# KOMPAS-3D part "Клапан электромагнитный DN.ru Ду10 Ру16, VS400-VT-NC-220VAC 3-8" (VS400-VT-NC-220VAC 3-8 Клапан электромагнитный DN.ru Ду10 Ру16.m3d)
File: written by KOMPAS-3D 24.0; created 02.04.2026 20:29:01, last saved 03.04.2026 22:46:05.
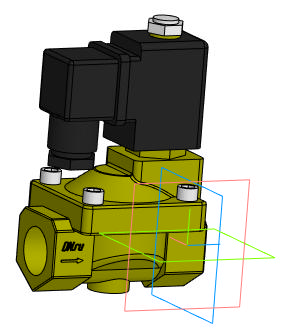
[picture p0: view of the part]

Document properties: Автор: artio; Полное имя файла: C:\Users\artio\OneDrive\Рабочий стол\Клапан электромагнитный DN.ru\VS400-VT-NC\VS400-VT-NC-220VAC 3-8 Клапан электромагнитный DN.ru Ду10 Ру16.m3d

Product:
- Body: Тело 1  | qty 1
    Масса: 1.030062
- Part/product: Клапан электромагнитный DN.ru Ду10 Ру16  | designation VS400-VT-NC-220VAC 3-8
    Масса: 0.797
    Раздел спецификации: Прочие изделия
    Примечание: D130-04697
    additional columns: ef56311e-7521-43dc-8291-0e6108b3d81d; VS400-ET-NC-220VAC 3-8; artio; c; Шероховатость не задана; Да

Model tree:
1. Операция без истории:1

Expressions: VS400-VT-NC-220VAC 3-8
